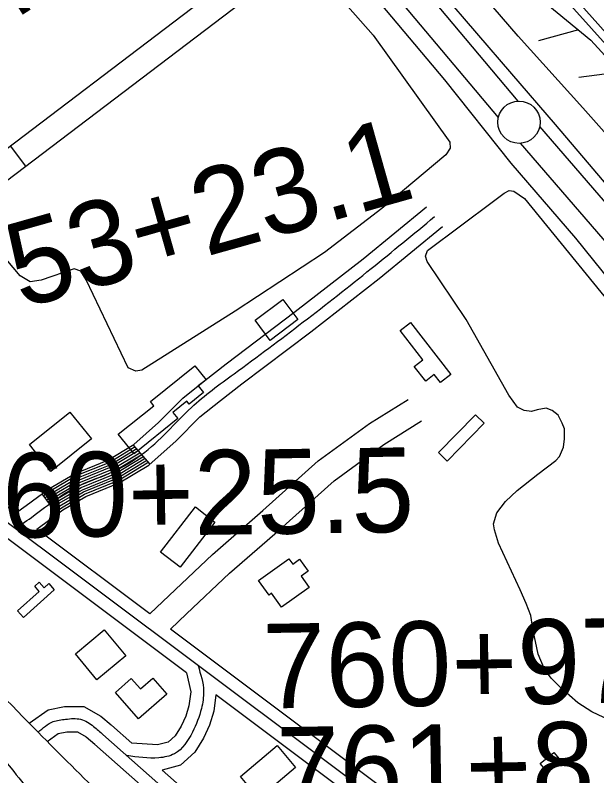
# Model space of a CAD drawing. Extents: x 3812694 to 3850888, y 319753 to 345638.
# Drawn here: x 3832872 to 3833560, y 327501 to 328399 of the extents above; entities that cross this region are included whole.
import ezdxf

# ---------------------------------------------------------------- set-up
doc = ezdxf.new("R2010")
doc.units = 0
for name, color, linetype in [('V-BLDG-OTLN', 7, 'Continuous'), ('V-LEVE-TOET', 7, 'Continuous'), ('V-RIVR-EDGE', 7, 'Continuous'), ('V-ROAD-CNTR', 7, 'Continuous'), ('V-RRAP-FSHR', 7, 'Continuous'), ('V-SITE-VEGE', 7, 'Continuous'), ('V-SURV-IDEN', 7, 'Continuous'), ('V-SURV-LINE', 7, 'Continuous'), ('V-TOPO-MINR', 7, 'Continuous'), ('V-WETL-SWMP', 7, 'Continuous')]:
    doc.layers.add(name, color=color, linetype=linetype)

msp = doc.modelspace()

# ---------------------------------------------------------------- linework, layer by layer
at = {"layer": 'V-BLDG-OTLN'}
for points in [[(3833206.44, 328039.63), (3833173.53, 328015.18), (3833155.74, 328039.12), (3833188.65, 328063.57)], [(3833339.58, 328036.34), (3833387.25, 327974.85), (3833374.97, 327965.33), (3833367.56, 327974.88), (3833357.39, 327966.99), (3833343.93, 327984.36), (3833353.98, 327992.16), (3833327.18, 328026.73)], [(3833064.34, 327922.76), (3833012.65, 327881.12), (3832994.09, 327904.16), (3833036.03, 327937.95), (3833031.98, 327942.98), (3833084.44, 327985.24), (3833097.77, 327968.7), (3833088.5, 327961.23), (3833094.81, 327953.41), (3833078.01, 327939.89), (3833075.25, 327943.31), (3833058.6, 327929.88)], [(3832962.3, 327898.74), (3832914.53, 327860.3), (3832889.01, 327892.02), (3832936.78, 327930.46)], [(3833426.58, 327917.22), (3833382.83, 327872.51), (3833372.65, 327882.46), (3833416.4, 327927.18)], [(3833108.32, 327800.4), (3833067.04, 327747.03), (3833043.84, 327764.97), (3833085.13, 327818.34)], [(3833208.33, 327756.46), (3833218.36, 327742.35), (3833210.05, 327736.45), (3833219.53, 327723.11), (3833186.79, 327699.84), (3833175.13, 327716.24), (3833172.21, 327714.16), (3833159.86, 327731.54), (3833195.75, 327757.04), (3833200.25, 327750.71)], [(3832918.42, 327720.53), (3832882.05, 327687.74), (3832875.08, 327695.47), (3832900.65, 327718.51), (3832895.23, 327724.52), (3832900.47, 327729.25), (3832906.42, 327722.65), (3832911.99, 327727.67)], [(3832943.34, 327644.57), (3832977.4, 327672.98), (3833002.84, 327642.49), (3832968.79, 327614.07)], [(3833051.29, 327597.16), (3833018.03, 327567.97), (3832990.71, 327599.09), (3833009.36, 327615.46), (3833020.14, 327603.18), (3833034.74, 327616.01)], [(3833203.66, 327510.24), (3833160.25, 327473.85), (3833138.41, 327499.91), (3833181.82, 327536.3)], [(3833516.95, 327518.38), (3833500.91, 327505.18), (3833492.81, 327515.03), (3833508.85, 327528.23)]]:
    msp.add_lwpolyline(points, close=True, dxfattribs=at)
at = {"layer": 'V-LEVE-TOET'}
for points in [[(3833275.1, 328447.63), (3833379.5, 328323.21), (3833458.16, 328224.56), (3833534.34, 328135.96), (3833631, 328016.19)], [(3833654.35, 328101.14), (3833555.36, 328217.92), (3833510.97, 328270.15), (3833459.38, 328330), (3833376.6, 328426.82)]]:
    msp.add_lwpolyline(points, dxfattribs=at)
at = {"layer": 'V-RIVR-EDGE'}
for points in [[(3833104.3, 333483.62), (3833118.76, 333479.07), (3833140.47, 333482.63), (3833153.15, 333489.38), (3833159.94, 333493.89), (3833169.89, 333495.22), (3833178.04, 333496.1), (3833190.71, 333503.3), (3833205.19, 333507.79), (3833219.22, 333510.92), (3833233.7, 333514.05), (3833239.58, 333518.56), (3833245.93, 333524.42), (3833255.89, 333530.72), (3833273.54, 333534.75), (3833296.61, 333538.31), (3833314.24, 333539.62), (3833330.07, 333540.04), (3833340.92, 333540.91), (3833350.42, 333540.89), (3833361.26, 333538.6), (3833370.3, 333534.96), (3833377.06, 333528.16), (3833377.05, 333520.93), (3833375.2, 333505.56), (3833375.63, 333495.61), (3833377.88, 333492.44), (3833378.31, 333482.95), (3833375.57, 333473.46), (3833382.78, 333460.78), (3833394.95, 333446.73), (3833407.57, 333429.07), (3833421.55, 333417.28), (3833431.02, 333406.85), (3833432.8, 333393.28), (3833431.86, 333380.17), (3833429.11, 333365.26), (3833419.13, 333352.17), (3833409.18, 333349.93), (3833384.31, 333348.19), (3833360.78, 333343.27), (3833340.86, 333333.83), (3833328.18, 333325.72), (3833324.09, 333316.68), (3833324.07, 333308.55), (3833318.62, 333300.42), (3833303.67, 333287.8), (3833286, 333270.66), (3833268.32, 333255.33), (3833249.32, 333250.85), (3833233.95, 333249.54), (3833211.8, 333252.3), (3833201.39, 333251.43), (3833195.5, 333244.66), (3833195.03, 333239.23), (3833199.07, 333223.85), (3833187.76, 333222.07), (3833182.77, 333217.56), (3833183.21, 333210.78), (3833185.46, 333208.51), (3833194.49, 333203.97), (3833201.27, 333202.59), (3833212.56, 333194.88), (3833230.15, 333179.01), (3833246.37, 333155.91), (3833255.82, 333134.18), (3833255.76, 333112.03), (3833258, 333102.53), (3833264.75, 333089.85), (3833278.71, 333068.56), (3833279.57, 333049.57), (3833291.68, 333010.2), (3833301.52, 332967.22), (3833323.09, 332912.91), (3833341.98, 332870.81), (3833357.71, 332833.24), (3833382.9, 332778.92), (3833424.32, 332706.02), (3833444.56, 332662.57), (3833494.06, 332568.85), (3833536.34, 332478.31), (3833559.29, 332433.94), (3833587.2, 332381.42), (3833635.75, 332267.36), (3833656.89, 332221.64), (3833682.51, 332160.98), (3833710.84, 332097.16), (3833742.34, 332038.75), (3833760.35, 332008.41), (3833810.32, 331918.31), (3833845.4, 331842.71), (3833866.54, 331796.09), (3833928.65, 331679.73), (3833972.76, 331600.04), (3834008.8, 331543.43), (3834062.82, 331448.35), (3834090.27, 331396.28), (3834119.99, 331343.76), (3834135.3, 331321.11), (3834208.74, 331214.22), (3834258.76, 331146.27), (3834291.65, 331097.36), (3834318.23, 331059.76), (3834350.67, 331012.66), (3834383.12, 330969.62), (3834409.26, 330935.65), (3834432.71, 330907.55), (3834501.69, 330827.8), (3834540.92, 330782.94), (3834577.43, 330738.54), (3834601.78, 330712.71), (3834674.37, 330627.97), (3834723.53, 330574.95), (3834769.08, 330527.36), (3834852.52, 330443.5), (3834911.59, 330378.7), (3834942.24, 330340.19), (3834962.95, 330302.61), (3834984.54, 330257.34), (3835000.63, 330181.79), (3835013.18, 330135.19), (3835021.71, 330112.56), (3835046.4, 330041.51), (3835070.27, 330000.75), (3835095.5, 329965.88), (3835137, 329925.98), (3835174.02, 329902.38), (3835220.99, 329879.2), (3835279.28, 329864.14), (3835326.3, 329861.76), (3835341.21, 329855.85), (3835345.25, 329846.79), (3835350.64, 329830.05), (3835351.9, 329792.97), (3835353.13, 329739.16), (3835359.36, 329699.35), (3835363.33, 329658.65), (3835368.22, 329627.44), (3835382.15, 329590.33), (3835402.41, 329554.56), (3835426.72, 329513.35), (3835450.15, 329478.48), (3835495.7, 329430.43), (3835554.31, 329362.01), (3835603.45, 329305.82), (3835640.43, 329263.23), (3835727.48, 329177.56), (3835794.7, 329116.35), (3835867.79, 329050.15), (3836008.13, 328937.22), (3836097.48, 328866.91), (3836157.05, 328817.93), (3836248.67, 328749.43), (3836313.67, 328705.86), (3836373.25, 328663.66), (3836428.31, 328620.12), (3836459.87, 328584.32), (3836495.97, 328554.39), (3836579.47, 328496.76), (3836648.53, 328445.49), (3836706.75, 328403.75), (3836825.04, 328331.11), (3836898.63, 328284.81), (3836957.77, 328248.04), (3837001.1, 328219.45), (3837095.46, 328161.79), (3837155.97, 328126.82), (3837218.26, 328084.62), (3837287.32, 328037.42), (3837394.73, 327954.87), (3837466.96, 327905.85), (3837528.33, 327859.13), (3837601.91, 327808.76), (3837768.48, 327697.57), (3837823.11, 327664.88), (3837892.2, 327625.82), (3838071.44, 327517.76), (3838161.28, 327460.57), (3838196.94, 327438.78), (3838361.26, 327329.4), (3838461.02, 327262.23), (3838503.01, 327236.36), (3838647.02, 327146.93), (3838732.8, 327094.26), (3838812.28, 327051.11), (3838945.94, 326981.6), (3839064.27, 326925.24), (3839131.11, 326892.07), (3839262.96, 326818.04), (3839338.36, 326776.71), (3839410.61, 326738.1), (3839451.72, 326720.36), (3839532.59, 326696.2), (3839590.89, 326683.39), (3839647.86, 326682.8), (3839668.65, 326680.03), (3839684.46, 326671.4), (3839707.02, 326653.26), (3839727.32, 326634.22), (3839753.96, 326620.14), (3839781.07, 326612.38), (3839814.52, 326608.68), (3839837.6, 326614.05), (3839860.24, 326628.47), (3839878.78, 326629.78), (3839887.37, 326627.95), (3839888.26, 326621.16), (3839878.25, 326597.22), (3839878.66, 326581.85), (3839885.43, 326574.6), (3839891.29, 326568.25), (3839900.32, 326561.9), (3839914.33, 326559.15), (3839939.62, 326545.52), (3839951.8, 326537.81), (3839971.23, 326529.17), (3839990.67, 326527.76), (3840012.35, 326518.21), (3840032.22, 326508.22), (3840065.61, 326483.27), (3840085.92, 326465.58), (3840104.87, 326450.61), (3840131.92, 326419.8), (3840146.35, 326403.03), (3840175.24, 326383.52), (3840213.61, 326355.84), (3840249.71, 326326.82), (3840303.87, 326287.34), (3840342.21, 326250.63), (3840394.54, 326201.21), (3840437.85, 326163.12), (3840482.09, 326133.62), (3840535.33, 326086.92), (3840561.5, 326064.25), (3840584.07, 326048.82), (3840611.62, 326036.09), (3840639.16, 326017.93), (3840725.78, 325940.4), (3840776.32, 325900.94), (3840832.75, 325862.36), (3840876.99, 325833.32), (3840964.57, 325776.58), (3841011.5, 325740.29), (3841058.02, 325718.47), (3841084.68, 325709.36)], [(3832461.73, 329674.16), (3832494.43, 329636.8), (3832515.58, 329611.67), (3832532.25, 329593.63), (3832563.67, 329560.12), (3832574.56, 329543.38), (3832594.43, 329518.9), (3832609.18, 329506.65), (3832631.01, 329496.95), (3832650.91, 329485.33), (3832659.89, 329474.38), (3832670.78, 329458.28), (3832688.73, 329440.24), (3832722.74, 329413.15), (3832744.56, 329400.24), (3832768.3, 329379.61), (3832795.23, 329349.97), (3832817.65, 329320.35), (3832830.46, 329300.39), (3832850.97, 329275.26), (3832874.66, 329237.28), (3832895.81, 329210.22), (3832913.75, 329185.75), (3832936.17, 329152.91), (3832962.45, 329121.34), (3832984.88, 329094.29), (3833007.32, 329068.52), (3833025.91, 329047.25), (3833047.08, 329030.49), (3833070.81, 329006), (3833097.09, 328975.08), (3833123.37, 328943.51), (3833141.3, 328915.82), (3833163.09, 328886.84), (3833175.27, 328872.67), (3833189.39, 328862.99), (3833201.6, 328860.39), (3833210.59, 328857.79), (3833220.87, 328853.91), (3833227.27, 328844.25), (3833242.65, 328823.64), (3833262.52, 328801.09), (3833288.81, 328772.1), (3833315.1, 328743.75), (3833359.33, 328695.42), (3833389.46, 328658.06), (3833417.66, 328625.85), (3833445.87, 328595.56), (3833456.75, 328575.61), (3833466.36, 328560.16), (3833484.94, 328536.97), (3833501.63, 328526), (3833522.18, 328515.02), (3833527.31, 328509.22), (3833534.99, 328498.91), (3833546.52, 328480.24), (3833574.71, 328440.31), (3833580.47, 328431.94), (3833588.82, 328427.42), (3833599.09, 328420.32), (3833609.34, 328405.51), (3833625.35, 328381.69), (3833658.04, 328344.32), (3833683.06, 328321.11), (3833708.69, 328289.55), (3833762.51, 328215.49), (3833806.75, 328165.23), (3833845.85, 328120.78), (3833872.12, 328083.43), (3833897.13, 328057.65), (3833915.07, 328035.75), (3833942.63, 327999.68), (3833963.12, 327969.41), (3833974.02, 327954.6), (3833984.93, 327947.5), (3833991.35, 327944.92), (3833999.06, 327945.54), (3834009.36, 327947.44), (3834017.07, 327947.42), (3834024.78, 327944.83), (3834037.6, 327931.3), (3834056.83, 327906.18), (3834062.59, 327898.45), (3834067.06, 327886.87), (3834064.45, 327868.23), (3834062.47, 327847.02), (3834061.13, 327828.38), (3834062.38, 327812.31), (3834065.55, 327796.23), (3834078.37, 327780.77), (3834092.46, 327757.59), (3834092.44, 327751.16), (3834089.85, 327742.81), (3834088.54, 327731.24), (3834088.46, 327701.67), (3834086.49, 327682.39), (3834083.84, 327653.47), (3834077.37, 327636.77), (3834068.33, 327620.72), (3834059.96, 327613.02), (3834049.66, 327607.91), (3834021.35, 327597.69), (3834015.55, 327592.56), (3834012.97, 327587.43), (3834009.72, 327574.58), (3834005.85, 327571.37), (3833993.63, 327568.83), (3833987.19, 327563.06), (3833980.1, 327554.08), (3833978.15, 327545.73), (3833978.14, 327541.87), (3833978.12, 327536.08), (3833981.32, 327529.65), (3833984.52, 327522.57)]]:
    msp.add_spline(points, degree=3, dxfattribs=at)
at = {"layer": 'V-ROAD-CNTR'}
for p, q in [((3832866.38, 328245.08), (3832884.53, 328221.2)), ((3833011.52, 327891.47), (3833031.36, 327868.97)), ((3832903.67, 327833.71), (3832921.47, 327809.56))]:
    msp.add_line(p, q, dxfattribs=at)
for points in [[(3832596.85, 328013.17), (3832629.12, 328043.75), (3832654.28, 328075.14), (3832693.85, 328109.47), (3832746.36, 328153.86), (3833174.22, 328479.07), (3833232.03, 328522.63)], [(3832625.2, 327998.7), (3832651.25, 328023.38), (3832676, 328054.26), (3832713.36, 328086.68), (3832765.13, 328130.45), (3833192.32, 328455.14), (3833250.09, 328498.67)], [(3832872.62, 327811.07), (3832885.17, 327820.08), (3832911.91, 327839.78), (3832942.28, 327857.56), (3832981.76, 327873.63), (3833012.25, 327892.12), (3833041.7, 327918.09), (3833070.36, 327946.99), (3833096.21, 327967.69), (3833121.76, 327987.52), (3833203.21, 328049.11), (3833283.53, 328111.68), (3833320.92, 328142.28), (3833358.44, 328173)], [(3832897.86, 327792.16), (3832928.43, 327814.69), (3832955.58, 327830.58), (3832995.28, 327846.74), (3833030.09, 327867.85), (3833062.29, 327896.26), (3833090.45, 327924.65), (3833114.78, 327944.13), (3833140, 327963.71), (3833221.48, 328025.31), (3833302.26, 328088.23), (3833339.92, 328119.07), (3833377.45, 328149.79)], [(3833357.46, 327429.04), (3832703.68, 327918.91), (3832602.18, 327997.56)], [(3832872.62, 327811.07), (3832712.78, 327930.84), (3832625.2, 327998.7)], [(3833074.82, 327622.08), (3832694.59, 327906.98), (3832596.4, 327983.06)], [(3833031.52, 327692.01), (3833054.2, 327713.54), (3833105.3, 327762.16), (3833165.02, 327814.22), (3833230.42, 327872.62), (3833291.02, 327916.81), (3833336.62, 327945.34)], [(3833055.87, 327673.76), (3833074.87, 327691.79), (3833125.51, 327739.97), (3833184.87, 327791.73), (3833249.29, 327849.25), (3833307.84, 327891.94), (3833352.53, 327919.9)], [(3832905.45, 327831.3), (3832913.56, 327837.27), (3832943.61, 327854.86), (3832983.11, 327870.94), (3833014.04, 327889.69)], [(3832907.23, 327828.88), (3832915.21, 327834.76), (3832944.94, 327852.16), (3832984.46, 327868.25), (3833015.82, 327887.26)], [(3832909.01, 327826.46), (3832916.87, 327832.25), (3832946.27, 327849.46), (3832985.82, 327865.56), (3833017.6, 327884.84)], [(3832910.79, 327824.05), (3832918.52, 327829.74), (3832947.6, 327846.77), (3832987.17, 327862.87), (3833019.39, 327882.41), (3833019.46, 327882.47)], [(3832912.57, 327821.63), (3832920.17, 327827.23), (3832948.93, 327844.07), (3832988.52, 327860.18), (3833021.17, 327879.98), (3833021.44, 327880.22)], [(3832914.35, 327819.22), (3832921.82, 327824.72), (3832950.26, 327841.37), (3832989.87, 327857.5), (3833022.95, 327877.56), (3833023.42, 327877.97)], [(3832916.13, 327816.8), (3832923.47, 327822.22), (3832951.59, 327838.67), (3832991.22, 327854.81), (3833024.74, 327875.13), (3833025.41, 327875.72)], [(3832917.91, 327814.39), (3832925.13, 327819.71), (3832952.92, 327835.97), (3832992.57, 327852.12), (3833026.52, 327872.7), (3833027.39, 327873.47)], [(3832919.69, 327811.97), (3832926.78, 327817.2), (3832954.25, 327833.28), (3832993.93, 327849.43), (3833028.3, 327870.28), (3833029.37, 327871.22)], [(3833031.52, 327692.01), (3832897.86, 327792.16)], [(3833379.89, 327430.98), (3833055.87, 327673.76)], [(3833074.82, 327622.08), (3833079.69, 327599.69), (3833077.58, 327583.39), (3833073.74, 327571.22), (3833068.35, 327559.15), (3833061.31, 327547.67), (3833053.09, 327540.19), (3833040.59, 327536.97), (3833010.21, 327539.09)], [(3833109.47, 327596.11), (3833106.99, 327576.91), (3833101.83, 327560.56), (3833094.95, 327545.13), (3833084.65, 327528.35), (3833067.78, 327512.99), (3833046.04, 327507.39)], [(3833348.46, 327417.04), (3833109.47, 327596.11)], [(3832888.64, 327562.86), (3832911.06, 327578.7), (3832930.43, 327582.45), (3832953.51, 327582.37), (3832973.51, 327571.22), (3832985.72, 327560.75)], [(3832985.9, 327560.6), (3833010.21, 327539.09)], [(3832909.92, 327541.16), (3832923.1, 327550.47), (3832933.25, 327552.44), (3832945.66, 327552.39), (3832956.28, 327546.48), (3832966.21, 327537.97)], [(3832975.96, 327549.36), (3833359.66, 327209.87)], [(3832966.02, 327538.13), (3833349.72, 327198.63)], [(3833046.04, 327507.39), (3833369.6, 327221.1)]]:
    msp.add_lwpolyline(points, dxfattribs=at)
for points in [[(3832872.42, 327792.48), (3832893.99, 327807.94), (3832920.17, 327827.23), (3832948.93, 327844.07), (3832988.52, 327860.18), (3833021.17, 327879.98), (3833052, 327907.17), (3833080.41, 327935.82), (3833130.88, 327975.62), (3833292.89, 328099.96), (3833367.94, 328161.39)], [(3833052.21, 327407.22), (3832973.63, 327478.64), (3832894.34, 327557.06), (3832793.12, 327664.58), (3832720.84, 327751.89), (3832638.6, 327854.31)], [(3833088.29, 327630.73), (3833094.89, 327600.34), (3833092.29, 327580.15), (3833081.65, 327552.14), (3833060.44, 327526.59), (3833041.98, 327521.83), (3833004.08, 327524.48)], [(3832833.52, 327621.67), (3832841.53, 327566.99), (3832852.39, 327531.43), (3832867.32, 327509.67), (3832892.38, 327478.97)], [(3832899.38, 327552.08), (3832917.08, 327564.59), (3832931.84, 327567.44), (3832949.59, 327567.38), (3832964.9, 327558.85), (3832975.96, 327549.36)]]:
    msp.add_spline(points, degree=3, dxfattribs=at)
at = {"layer": 'V-RRAP-FSHR'}
for p, q in [((3833537.91, 328382.01), (3833490.84, 328369.01)), ((3833586.92, 328332.23), (3833538.49, 328325.97))]:
    msp.add_line(p, q, dxfattribs=at)
for points in [[(3831986.32, 330273.3), (3832264.59, 329899.92), (3832553.04, 329546.93), (3832730.05, 329375.71), (3833064.17, 328942.2), (3833134.11, 328900.74), (3833477.84, 328482.43), (3833770.04, 328155.42), (3833951.11, 327952.13)], [(3833483.94, 328426.59), (3833552.56, 328369.91), (3833611.25, 328305.55), (3833703.25, 328196.52)]]:
    msp.add_lwpolyline(points, dxfattribs=at)
at = {"layer": 'V-SITE-VEGE'}
for points in [[(3833265.3, 328409.86), (3833295.21, 328375.92), (3833385.81, 328249.28), (3833386.48, 328242.19), (3833381.24, 328234.46), (3833305.71, 328171), (3833237.73, 328118.85), (3833132.13, 328049.76), (3833021.8, 327980.01), (3833014.73, 327978.76), (3833005.82, 327982.79), (3832956.23, 328086.84), (3832949.63, 328096.81), (3832941.92, 328099.68), (3832903.06, 328086.26), (3832890.09, 328084.35), (3832878.19, 328091.31), (3832815.94, 328165.08), (3832749.7, 328279.58), (3832663.31, 328399.18), (3832662.04, 328406.85)], [(3833574.63, 327566.51), (3833553.85, 327576.33), (3833537.19, 327586.78), (3833517.5, 327604.29), (3833505.55, 327615.98), (3833497.75, 327626.53), (3833490.48, 327644.18), (3833484.26, 327672.47), (3833481.7, 327690.17), (3833476.23, 327704.29), (3833468.97, 327720.16), (3833443.55, 327775.43), (3833438.65, 327791.33), (3833437.39, 327798.41), (3833441.39, 327811.45), (3833451.88, 327824.57), (3833465.32, 327837.71), (3833489.93, 327856.89), (3833511.03, 327873.07), (3833515.7, 327877.85), (3833520.31, 327889.12), (3833521.39, 327898.59), (3833521.26, 327910.41), (3833518.82, 327917.47), (3833513.99, 327926.87), (3833506.84, 327932.11), (3833499.72, 327934.99), (3833489.1, 327933.1), (3833482.62, 327931.26), (3833473.75, 327932.34), (3833466.02, 327936.4), (3833455.83, 327950.46), (3833405.22, 328039.73), (3833358.98, 328108.36), (3833357.13, 328114.84), (3833359.43, 328121.36), (3833437.38, 328179.52), (3833450.28, 328189.12), (3833456.15, 328192.13), (3833461.48, 328191.6), (3833473.98, 328182.88), (3833599.14, 328029.43)]]:
    msp.add_lwpolyline(points, dxfattribs=at)
at = {"layer": 'V-SURV-LINE'}
for points in [[(3833181.71, 328636.55), (3833466.31, 328297.93)], [(3833443.34, 328278.62), (3833158.74, 328617.25)], [(3833492.08, 328267.69), (3833925.33, 327766.51)], [(3833902.64, 327746.88), (3833469.39, 328248.06)]]:
    msp.add_lwpolyline(points, dxfattribs=at)
msp.add_circle((3833467.68, 328272.99), 25, dxfattribs=at)
at = {"layer": 'V-TOPO-MINR'}
msp.add_lwpolyline([(3833045.58, 328949.51), (3833061.6, 328932.09), (3833067.54, 328925.62), (3833073.48, 328919.16), (3833079.42, 328912.69), (3833085.36, 328906.23), (3833094.45, 328896.34), (3833095.84, 328894.81), (3833098.62, 328891.76), (3833100, 328890.23), (3833120.83, 328867.1), (3833132.57, 328853.95), (3833144.22, 328840.72), (3833155.74, 328827.39), (3833167.19, 328813.98), (3834262.74, 327593.9)], dxfattribs=at)
at = {"layer": 'V-WETL-SWMP'}
for p, q in [((3833466.52, 328374.59), (3833362.25, 328497.29)), ((3833543.16, 328289.85), (3833466.52, 328374.59)), ((3833604.25, 328221.1), (3833543.16, 328289.85))]:
    msp.add_line(p, q, dxfattribs=at)

# ---------------------------------------------------------------- texts
at = {"layer": 'V-SURV-IDEN'}
for s, rotation, p in [('748+40.8', 32.46669, (3832587.82, 328213.41)), ('753+23.1', 15.78121, (3832807.73, 328032.08)), ('760+25.5', 0.83716, (3832782.96, 327780.7)), ('760+97.0', 0.95058, (3833165.38, 327580.02)), ('761+81.3', 1.05179, (3833182.11, 327457.94))]:
    msp.add_text(s, height=100, rotation=rotation, dxfattribs=at).set_placement(p)

doc.saveas('drawing.dxf')
